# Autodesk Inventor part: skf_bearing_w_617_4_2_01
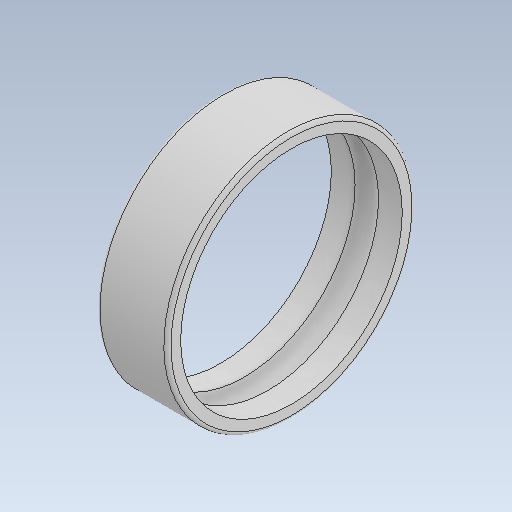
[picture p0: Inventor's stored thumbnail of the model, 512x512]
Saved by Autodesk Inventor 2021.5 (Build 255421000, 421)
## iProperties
Created: 2023-11
Part Number: skf_bearing_w_617_4_2_01
Checked By: TraceParts S.A.
Material: Generic
Catalog Web Link: www.traceparts.com
Document SubType Name: Modeling
Designer: TraceParts
Density: 1 g/cm^3
Appearance: Default
Company: TraceParts S.A.
Author: TraceParts
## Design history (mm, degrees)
feature "skf_bearing_w_617_4_2_01.ipt"
body "Solid1"
